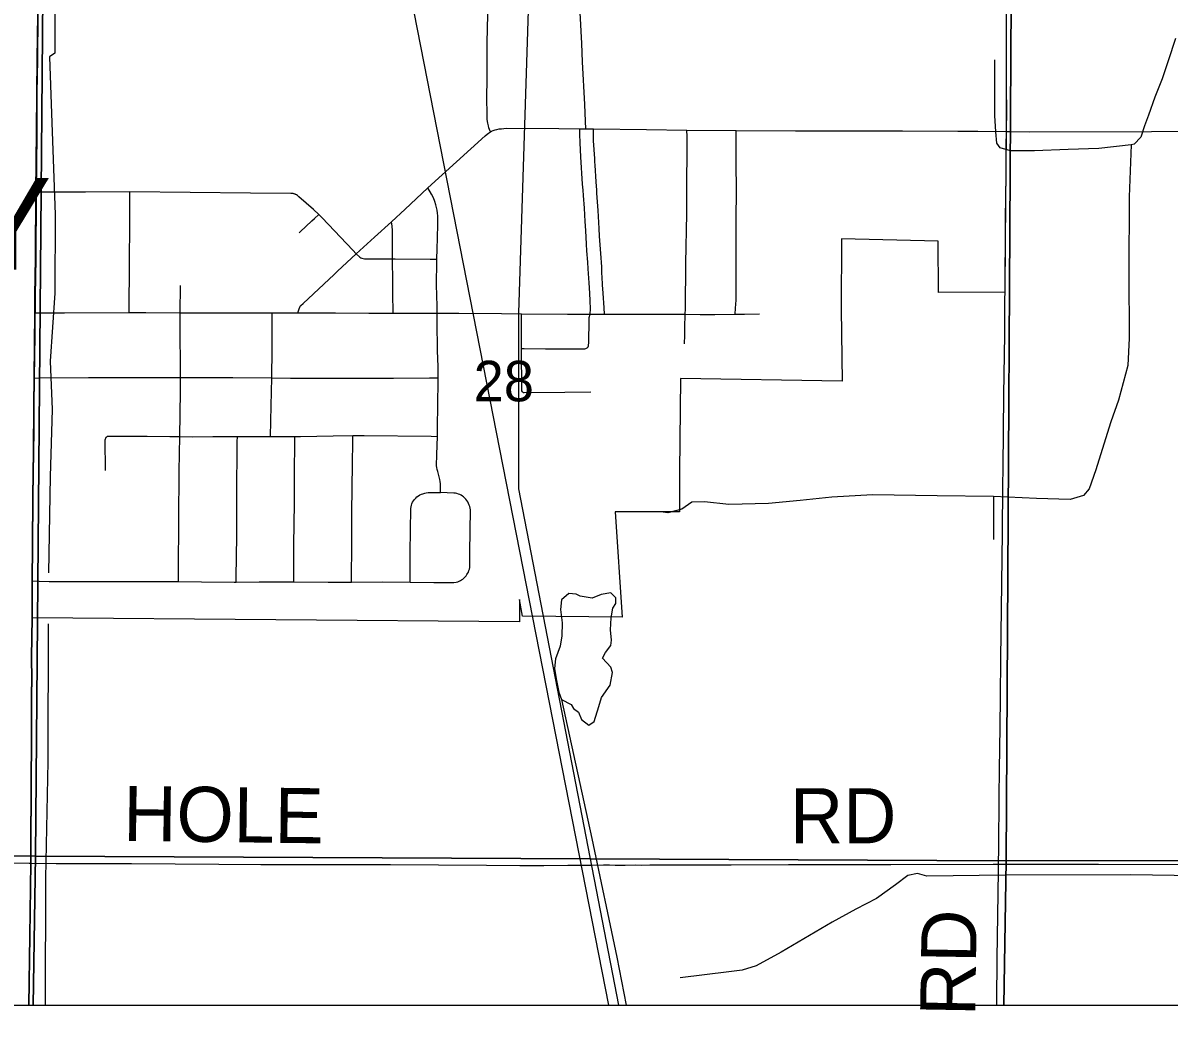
# Model space of a CAD drawing. Extents: x 0 to 34, y 0 to 22.
# Drawn here: x 3.48 to 4.664, y 16.867 to 17.907 of the extents above; entities that cross this region are included whole.
import ezdxf

# ---------------------------------------------------------------- set-up
doc = ezdxf.new("R2010")
doc.units = 0
for name, color, linetype in [('GM_X_City_Street', 7, 'Continuous'), ('GM_X_Corporation', 7, 'Continuous'), ('GM_X_Corporation_Text', 7, 'Continuous'), ('GM_X_County_Road', 7, 'Continuous'), ('GM_X_Minor_Lake', 7, 'Continuous'), ('GM_X_Minor_River', 7, 'Continuous'), ('GM_X_Rail_Line', 7, 'Continuous'), ('GM_X_Section', 7, 'Continuous'), ('GM_X_Section_Text', 7, 'Continuous'), ('GM_X_State_Route', 7, 'Continuous'), ('GM_X_Township_Road', 7, 'Continuous'), ('GM_X_Township_Road_Text', 7, 'Continuous'), ('GM_X_US_Route', 7, 'Continuous'), ('SH_Text', 7, 'Continuous')]:
    doc.layers.add(name, color=color, linetype=linetype)

msp = doc.modelspace()

# ---------------------------------------------------------------- linework, layer by layer
at = {"layer": 'GM_X_City_Street'}
for points in [[(3.963, 17.795), (3.962, 17.7976), (3.9614, 17.7993), (3.9608, 17.8014), (3.9601, 17.8039), (3.9596, 17.8077), (3.9595, 17.8114), (3.9592, 17.832), (3.9594, 17.8479), (3.9596, 17.887), (3.9613, 17.9602), (3.9621, 17.9987), (3.9626, 18.0388), (3.9627, 18.0507)], [(4.0615, 17.7983), (4.0611, 17.8059), (4.0603, 17.8233), (4.0581, 17.8673), (4.0572, 17.8864), (4.0555, 17.9181), (4.0549, 17.9286), (4.0539, 17.9459), (4.0535, 17.9527), (4.053, 17.9627), (4.0514, 17.993), (4.051, 18.0017), (4.0497, 18.024), (4.0492, 18.0399), (4.0488, 18.0504)], [(4.0658, 17.607), (4.0664, 17.6125), (4.0659, 17.6206), (4.0654, 17.6286), (4.0648, 17.6393), (4.0638, 17.6535), (4.0634, 17.6604), (4.0626, 17.6721), (4.0622, 17.679), (4.0613, 17.6932), (4.0607, 17.7025), (4.0599, 17.7162), (4.0591, 17.7292), (4.0586, 17.7347), (4.0581, 17.7412), (4.0564, 17.7693), (4.0556, 17.7836), (4.0554, 17.7927), (4.0554, 17.7983)], [(4.0806, 17.6068), (4.0802, 17.6135), (4.0793, 17.6286), (4.0787, 17.6373), (4.0783, 17.6453), (4.0781, 17.649), (4.078, 17.6508), (4.0779, 17.6533), (4.0778, 17.6557), (4.0769, 17.6694), (4.0757, 17.6873), (4.0751, 17.6953), (4.0747, 17.7014), (4.074, 17.7137), (4.0729, 17.7317), (4.0727, 17.7347), (4.0721, 17.7433), (4.071, 17.7606), (4.0708, 17.7641), (4.0706, 17.7665), (4.0706, 17.7676), (4.0695, 17.7858), (4.0693, 17.7911), (4.0693, 17.7928), (4.0694, 17.7982)], [(4.1632, 17.5763), (4.1635, 17.5851), (4.1637, 17.5931), (4.1639, 17.6069), (4.1642, 17.6123), (4.1647, 17.6596), (4.1656, 17.7104), (4.1657, 17.7436), (4.166, 17.7734), (4.1659, 17.7902), (4.1658, 17.7969)], [(4.2157, 17.6069), (4.2161, 17.6132), (4.2165, 17.6213), (4.2167, 17.6534), (4.2165, 17.6991), (4.2169, 17.7399), (4.2168, 17.7577), (4.2167, 17.7877), (4.2167, 17.7964)], [(3.4939, 17.733), (3.504, 17.7331), (3.545, 17.7332), (3.5907, 17.7334), (3.7152, 17.7321), (3.757, 17.7319), (3.7578, 17.7318), (3.7588, 17.7317), (3.7596, 17.7314), (3.7607, 17.731)], [(3.5899, 17.6085), (3.59, 17.6153), (3.5903, 17.6538), (3.5906, 17.7067), (3.5907, 17.7334)], [(3.8242, 17.6692), (3.8208, 17.673), (3.7893, 17.7062), (3.7857, 17.7096), (3.7801, 17.715), (3.7651, 17.7281), (3.7637, 17.7293), (3.7627, 17.73), (3.7617, 17.7305), (3.7607, 17.731)], [(3.9114, 17.4228), (3.9114, 17.4317), (3.9111, 17.4343), (3.9107, 17.4363), (3.9085, 17.4444), (3.908, 17.4464), (3.9077, 17.4486), (3.9074, 17.4504), (3.9077, 17.4621), (3.9082, 17.4806), (3.9084, 17.4895), (3.909, 17.5378), (3.9089, 17.5412), (3.9088, 17.5525), (3.9087, 17.5611), (3.9084, 17.5689), (3.9082, 17.5756), (3.9079, 17.5928), (3.9078, 17.6079), (3.9078, 17.615), (3.9074, 17.6373), (3.9075, 17.6611), (3.9076, 17.6636), (3.9079, 17.6743), (3.9084, 17.6854), (3.9085, 17.6997), (3.9085, 17.7082), (3.9082, 17.7112), (3.9078, 17.7141), (3.9072, 17.7171), (3.9066, 17.7198), (3.9055, 17.7232), (3.904, 17.727), (3.9022, 17.7306), (3.8984, 17.7373)], [(3.7656, 17.6908), (3.7665, 17.6917), (3.7787, 17.7032), (3.7813, 17.7056), (3.7857, 17.7096)], [(3.8619, 17.6639), (3.8618, 17.6812), (3.8617, 17.6945), (3.8616, 17.6964), (3.8614, 17.6978), (3.8608, 17.7022)], [(3.8242, 17.6692), (3.8281, 17.6657), (3.8291, 17.6651), (3.8303, 17.6646), (3.8315, 17.6643), (3.833, 17.6641), (3.835, 17.6641), (3.8619, 17.6639), (3.8647, 17.6639), (3.9006, 17.6637), (3.9076, 17.6636)], [(3.8624, 17.6079), (3.8622, 17.6286), (3.862, 17.6471), (3.8619, 17.6566), (3.8619, 17.6639)], [(3.6409, 17.3309), (3.6409, 17.343), (3.6416, 17.4448), (3.6422, 17.4806), (3.6428, 17.5269), (3.6428, 17.5416), (3.6429, 17.5513), (3.6427, 17.5896), (3.6426, 17.6084), (3.6428, 17.6363)], [(3.7359, 17.4805), (3.7366, 17.5123), (3.7374, 17.541), (3.7376, 17.5704), (3.7375, 17.6006), (3.7375, 17.6081)], [(3.7641, 17.6081), (3.8031, 17.6081), (3.8373, 17.608), (3.8624, 17.6079), (3.8745, 17.6079), (3.8937, 17.6078), (3.9078, 17.6079), (3.9304, 17.608), (3.9742, 17.6074), (3.995, 17.6072), (4.0424, 17.6067), (4.0658, 17.607), (4.0806, 17.6068), (4.0964, 17.6068), (4.1299, 17.6069), (4.1639, 17.6069), (4.1796, 17.6065), (4.1945, 17.6065), (4.2157, 17.6069), (4.2254, 17.607), (4.2408, 17.6072)], [(3.9959, 17.5268), (3.9952, 17.5278), (3.995, 17.5713), (3.995, 17.5997), (3.995, 17.6072)], [(3.995, 17.5713), (3.9977, 17.5713), (4.0197, 17.5711), (4.0604, 17.5711), (4.0614, 17.5714), (4.0621, 17.5717), (4.0628, 17.5721), (4.0633, 17.5726), (4.0638, 17.5733), (4.0641, 17.5742), (4.0643, 17.5751), (4.0645, 17.5769), (4.0647, 17.6012), (4.0649, 17.6034), (4.0658, 17.607)], [(3.4921, 17.5407), (3.4982, 17.5412), (3.5478, 17.5414), (3.597, 17.5414), (3.6428, 17.5416), (3.6969, 17.5416), (3.7374, 17.541), (3.7565, 17.5408), (3.8628, 17.5409), (3.9, 17.5411), (3.9089, 17.5412)], [(3.9959, 17.5268), (3.9967, 17.5261), (3.9977, 17.5259), (4.0399, 17.5264), (4.0667, 17.5267)], [(3.5654, 17.4454), (3.5653, 17.4773), (3.5655, 17.4781), (3.5658, 17.4788), (3.5663, 17.4799)], [(3.5663, 17.4799), (3.5668, 17.4804), (3.5674, 17.4808), (3.568, 17.481), (3.5687, 17.4811), (3.6086, 17.4808), (3.6319, 17.4807), (3.6422, 17.4806), (3.6551, 17.4804), (3.6763, 17.4807), (3.7018, 17.4806), (3.7235, 17.4805), (3.7359, 17.4805), (3.7484, 17.4806), (3.7611, 17.4807), (3.7669, 17.4807), (3.8007, 17.4813), (3.8208, 17.4815), (3.8325, 17.4816), (3.9019, 17.4808), (3.9082, 17.4806)], [(3.7005, 17.3304), (3.7005, 17.3354), (3.701, 17.3776), (3.7011, 17.4179), (3.7016, 17.4752), (3.7018, 17.4806)], [(3.7599, 17.3305), (3.7599, 17.3373), (3.7601, 17.3687), (3.7605, 17.4118), (3.7605, 17.4469), (3.7609, 17.4708), (3.7611, 17.4807)], [(3.8195, 17.3304), (3.8196, 17.3375), (3.8198, 17.3651), (3.8198, 17.4021), (3.8205, 17.4523), (3.8207, 17.475), (3.8208, 17.4815)], [(3.8799, 17.3301), (3.8799, 17.3371), (3.8801, 17.3609), (3.8809, 17.4063), (3.881, 17.4081), (3.8813, 17.4096), (3.8817, 17.4111), (3.8824, 17.4127), (3.8834, 17.4142), (3.8844, 17.4155), (3.8858, 17.4169), (3.8871, 17.4182), (3.8886, 17.4194), (3.8902, 17.4203), (3.8918, 17.4211), (3.8933, 17.4216), (3.8951, 17.4221), (3.8967, 17.4225), (3.8987, 17.4227), (3.9114, 17.4228)], [(3.9356, 17.3345), (3.9367, 17.3357), (3.9378, 17.3368), (3.9387, 17.3381), (3.9394, 17.3393), (3.9402, 17.3407), (3.9408, 17.3423), (3.9412, 17.3438), (3.9416, 17.3455), (3.9418, 17.3473), (3.9415, 17.3611), (3.9422, 17.405), (3.9421, 17.4067), (3.9417, 17.4082), (3.941, 17.4099), (3.9402, 17.4115), (3.9395, 17.413), (3.9385, 17.4146), (3.9376, 17.4159), (3.9364, 17.417), (3.9352, 17.4182), (3.9341, 17.419), (3.9328, 17.4199), (3.9314, 17.4206), (3.93, 17.4212), (3.9284, 17.4217), (3.9267, 17.4221), (3.925, 17.4222), (3.9114, 17.4228)], [(3.4901, 17.3315), (3.497, 17.3313), (3.5075, 17.3311), (3.5571, 17.3309), (3.582, 17.3308), (3.6292, 17.3308), (3.6409, 17.3309), (3.6646, 17.3306), (3.6982, 17.3304), (3.7005, 17.3304), (3.7242, 17.3305), (3.75, 17.3306), (3.7599, 17.3305), (3.7954, 17.3304), (3.8195, 17.3304), (3.8511, 17.3305), (3.8799, 17.3301), (3.9045, 17.3299), (3.9252, 17.33), (3.9274, 17.3303), (3.9292, 17.3307), (3.9306, 17.3312), (3.9319, 17.3319), (3.9332, 17.3327), (3.9344, 17.3335), (3.9356, 17.3345)]]:
    msp.add_lwpolyline(points, dxfattribs=at)
at = {"layer": 'GM_X_Corporation'}
msp.add_lwpolyline([(4.4959, 18.0466), (4.4954, 17.796), (4.4944, 17.6823), (4.4939, 17.6297), (4.4257, 17.6292), (4.4251, 17.6823), (4.3255, 17.6845), (4.3252, 17.6116), (4.3262, 17.5376), (4.1591, 17.5404), (4.1582, 17.4446), (4.1582, 17.403), (4.0917, 17.4028), (4.099, 17.2941), (3.9962, 17.2953), (3.993, 17.3122), (3.9929, 17.2963), (3.993, 17.2894), (3.4897, 17.2934), (3.4899, 17.3321), (3.4919, 17.5412), (3.4925, 17.6088), (3.4933, 17.665), (3.4936, 17.7336), (3.4944, 17.795), (3.4956, 17.9163)], dxfattribs=at)
at = {"layer": 'GM_X_County_Road'}
for points in [[(3.4939, 17.733), (3.4939, 17.736), (3.4942, 17.7596), (3.4946, 17.7944), (3.4947, 17.8349), (3.4952, 17.8697), (3.4958, 17.9157), (3.4964, 17.9723), (3.4966, 18.0071), (3.497, 18.0326), (3.4975, 18.0561)], [(3.4928, 17.6082), (3.4929, 17.6259), (3.4936, 17.6645), (3.4935, 17.6782), (3.4938, 17.7167), (3.4939, 17.733)], [(3.4921, 17.5407), (3.4927, 17.5848), (3.4928, 17.6082)], [(3.4901, 17.3315), (3.4904, 17.3674), (3.4908, 17.4178), (3.491, 17.4424), (3.4917, 17.4865), (3.4919, 17.5127), (3.4921, 17.5407)], [(3.4899, 17.2938), (3.4899, 17.3064), (3.4901, 17.3315)], [(3.4885, 17.0403), (3.4885, 17.0425), (3.4887, 17.0721), (3.489, 17.105), (3.489, 17.1211), (3.4891, 17.1367), (3.4892, 17.1528), (3.4893, 17.174), (3.4892, 17.1964), (3.4894, 17.2144), (3.4897, 17.2293), (3.4895, 17.2523), (3.4899, 17.2929), (3.4899, 17.2938)], [(3.4867, 16.8935), (3.4875, 16.9645), (3.4882, 17.0142), (3.4885, 17.0403)]]:
    msp.add_lwpolyline(points, dxfattribs=at)
at = {"layer": 'GM_X_Minor_Lake'}
msp.add_line((4.0681, 17.3138), (4.0556, 17.3157), dxfattribs=at)
msp.add_lwpolyline([(4.0556, 17.3157), (4.0515, 17.3177), (4.0439, 17.3186), (4.0362, 17.312), (4.0352, 17.3021), (4.0371, 17.2884), (4.0368, 17.2747), (4.035, 17.2642), (4.0301, 17.251), (4.0291, 17.2412), (4.0311, 17.2286), (4.0335, 17.2168), (4.0363, 17.2091), (4.0464, 17.2039), (4.0486, 17.1997), (4.0538, 17.1962), (4.057, 17.1885), (4.0644, 17.1826), (4.0702, 17.1863), (4.0748, 17.2021), (4.0776, 17.2111), (4.0867, 17.2238), (4.0889, 17.2371), (4.0871, 17.2424), (4.0786, 17.2517), (4.0818, 17.2577), (4.0873, 17.2648), (4.0878, 17.2705), (4.0869, 17.2811), (4.0876, 17.2936), (4.0894, 17.3035), (4.0925, 17.3083), (4.0923, 17.314), (4.0871, 17.3191), (4.0772, 17.3174), (4.0681, 17.3138)], dxfattribs=at)
at = {"layer": 'GM_X_Minor_River'}
for points in [[(3.5164, 18.4352), (3.5149, 18.3401), (3.5141, 18.2475), (3.5142, 18.1295), (3.5133, 18.0316), (3.5132, 17.8764), (3.5078, 17.8723), (3.5098, 17.8139), (3.5136, 17.7098), (3.5131, 17.6286), (3.5084, 17.5585), (3.5105, 17.5083), (3.5084, 17.4393), (3.5067, 17.3399)], [(4.6701, 17.8913), (4.6628, 17.8683), (4.6566, 17.8499), (4.6488, 17.831), (4.6425, 17.8124), (4.6384, 17.8013), (4.6344, 17.7894), (4.6277, 17.7823), (4.6246, 17.7816), (4.591, 17.7779), (4.5594, 17.7767), (4.5245, 17.7756), (4.4999, 17.7755), (4.4893, 17.7786), (4.4857, 17.7834), (4.4848, 17.7952), (4.4837, 17.812), (4.4836, 17.8692)], [(4.6246, 17.7816), (4.6225, 17.7281), (4.6221, 17.6496), (4.6223, 17.582), (4.6209, 17.554), (4.6113, 17.5181), (4.6033, 17.4959), (4.5945, 17.4673), (4.5879, 17.4462), (4.581, 17.4267), (4.5751, 17.4196), (4.5614, 17.4157), (4.5266, 17.4166), (4.4823, 17.4188), (4.424, 17.4195), (4.3574, 17.4203), (4.3153, 17.4179), (4.2826, 17.4145), (4.25, 17.4115), (4.2092, 17.4103), (4.1838, 17.4131), (4.1709, 17.4127), (4.1605, 17.4057), (4.146, 17.4019), (4.1411, 17.4024)], [(4.4823, 17.4188), (4.4823, 17.3744)], [(3.5035, 16.8935), (3.5038, 17.0247), (3.5064, 17.1453), (3.5065, 17.2872)], [(4.0363, 17.2091), (4.0676, 17.0657), (4.0933, 16.9432), (4.103, 16.8935)], [(5.1426, 17.0309), (5.0559, 17.03), (4.9471, 17.0292), (4.8582, 17.0291), (4.7358, 17.0264), (4.6241, 17.0283), (4.4946, 17.028), (4.4135, 17.0269), (4.4037, 17.0295), (4.3938, 17.0274), (4.3811, 17.0179), (4.3614, 17.0039), (4.3403, 16.9927), (4.3158, 16.9792), (4.2631, 16.9482), (4.2374, 16.9344), (4.2229, 16.9299), (4.2092, 16.9279), (4.1587, 16.9219)]]:
    msp.add_lwpolyline(points, dxfattribs=at)
at = {"layer": 'GM_X_Rail_Line'}
for points in [[(3.0707, 20.9), (3.1351, 20.7649), (3.2934, 20.4339), (3.3742, 20.2628), (3.4243, 20.1498), (3.4485, 20.0723), (3.4792, 19.9786), (3.5083, 19.83), (3.6846, 18.9371), (3.8463, 18.1103), (4.0848, 16.8935)], [(4.0191, 20.9), (4.0122, 20.3656), (4.0051, 19.4649), (4.0042, 19.0681), (4.0247, 18.6307), (3.9918, 17.6084), (3.9918, 17.4265), (4.095, 16.8935)]]:
    msp.add_lwpolyline(points, dxfattribs=at)
at = {"layer": 'GM_X_Section'}
for points in [[(3.5019, 18.057), (3.4934, 17.0475), (2.4879, 17.0483), (2.4915, 18.0628)], [(4.5012, 18.0497), (4.4954, 17.0428), (3.4934, 17.0475), (3.5019, 18.057)], [(5.5052, 18.0545), (5.4985, 17.0434), (4.4954, 17.0428), (4.5012, 18.0497)]]:
    msp.add_lwpolyline(points, close=True, dxfattribs=at)
for points in [[(3.4773, 16.1435), (3.4754, 16.0365), (3.4686, 16.0366), (2.4803, 16.0422), (2.4865, 16.4094), (2.4879, 17.0483), (3.4934, 17.0475), (3.4907, 16.8935)], [(3.4907, 16.8935), (3.4934, 17.0475), (4.4954, 17.0428), (4.4929, 16.8935)], [(4.4929, 16.8935), (4.4954, 17.0428), (5.4985, 17.0434), (5.476, 16.0344), (5.457, 16.0346), (4.4786, 16.0375), (4.4803, 16.1435)]]:
    msp.add_lwpolyline(points, dxfattribs=at)
at = {"layer": 'GM_X_State_Route'}
for p, q in [((4.4454, 17.7958), (4.4663, 17.7956)), ((4.4663, 17.7956), (4.4957, 17.7954))]:
    msp.add_line(p, q, dxfattribs=at)
for points in [[(3.4975, 18.0561), (3.497, 18.0326), (3.4966, 18.0071), (3.4964, 17.9723), (3.4958, 17.9157), (3.4952, 17.8697), (3.4947, 17.8349), (3.4946, 17.7944), (3.4942, 17.7596), (3.4939, 17.736), (3.4939, 17.733)], [(3.8051, 17.6511), (3.8242, 17.6692), (3.8432, 17.6864), (3.8608, 17.7022), (3.8748, 17.7153), (3.8921, 17.7313), (3.8984, 17.7373), (3.9576, 17.791), (3.9595, 17.7926), (3.9609, 17.7937), (3.963, 17.795), (3.9641, 17.7956), (3.9657, 17.7963), (3.9677, 17.797), (3.9697, 17.7975), (3.9721, 17.798), (3.9745, 17.7983), (3.9767, 17.7986), (3.9792, 17.7987), (4.0337, 17.7985), (4.0554, 17.7983), (4.0615, 17.7983), (4.0694, 17.7982), (4.1239, 17.7973), (4.1658, 17.7969), (4.2167, 17.7964), (4.2778, 17.7962), (4.3884, 17.7961), (4.4454, 17.7958)], [(4.4957, 17.7954), (4.4991, 17.7954), (4.519, 17.7951), (4.6455, 17.7954), (4.7296, 17.7964), (4.7731, 17.7969), (4.8092, 17.7969), (4.875, 17.7975), (4.9073, 17.7979), (4.9501, 17.7976), (4.9868, 17.7977), (5.0076, 17.7978), (5.066, 17.7979), (5.1163, 17.7981), (5.1723, 17.7982), (5.217, 17.7983), (5.3339, 17.7983), (5.5041, 17.7977)], [(3.4939, 17.733), (3.4938, 17.7167), (3.4935, 17.6782), (3.4936, 17.6645), (3.4929, 17.6259), (3.4928, 17.6082)], [(3.7695, 17.6179), (3.8015, 17.6477), (3.8051, 17.6511)], [(3.4928, 17.6082), (3.5233, 17.6082), (3.5899, 17.6085), (3.5917, 17.6085), (3.607, 17.6085)], [(3.607, 17.6085), (3.6426, 17.6084), (3.6962, 17.6084), (3.7262, 17.6082)], [(3.7262, 17.6082), (3.7375, 17.6081), (3.7473, 17.6081), (3.7641, 17.6081), (3.7653, 17.6124), (3.766, 17.614), (3.7666, 17.615), (3.7673, 17.6159), (3.7695, 17.6179)]]:
    msp.add_lwpolyline(points, dxfattribs=at)
at = {"layer": 'GM_X_Township_Road'}
for points in [[(4.4957, 17.7954), (4.496, 17.8176), (4.4959, 17.8388), (4.4958, 17.868), (4.4961, 17.9965), (4.4966, 18.0464)], [(4.4942, 17.6292), (4.4947, 17.7018), (4.495, 17.7315), (4.4953, 17.7457), (4.4954, 17.7624), (4.4955, 17.781), (4.4957, 17.7954)], [(4.494, 17.6133), (4.4941, 17.6227), (4.4942, 17.6292)], [(4.4875, 17.0392), (4.4878, 17.0562), (4.4883, 17.109), (4.4884, 17.1364), (4.4891, 17.1811), (4.4894, 17.2116), (4.49, 17.2514), (4.4906, 17.3027), (4.4917, 17.3815), (4.492, 17.4292), (4.4924, 17.4485), (4.4931, 17.5237), (4.4939, 17.5858), (4.494, 17.607), (4.494, 17.6133)], [(2.4899, 17.0522), (2.5014, 17.0521), (2.548, 17.0515), (2.604, 17.0508), (2.6723, 17.0498), (2.7438, 17.0491), (2.7966, 17.0484), (2.8526, 17.0478), (2.8681, 17.0476), (2.921, 17.047), (2.952, 17.0465), (2.9614, 17.0463), (2.9987, 17.0459), (3.0919, 17.0449), (3.1447, 17.0443), (3.1851, 17.0439), (3.2411, 17.0432), (3.3343, 17.0421), (3.3623, 17.0417), (3.3965, 17.0412), (3.4617, 17.0405), (3.4866, 17.0403), (3.4885, 17.0403)], [(3.4885, 17.0403), (3.5146, 17.04), (3.5425, 17.0399), (3.5923, 17.0399), (3.6824, 17.0392), (3.7259, 17.0389), (3.7477, 17.0387), (3.816, 17.0389), (3.8596, 17.0388), (3.959, 17.0381), (3.9932, 17.0379), (3.9994, 17.0379), (4.0179, 17.0377), (4.0429, 17.038), (4.0628, 17.0382)], [(4.0628, 17.0382), (4.0667, 17.0382), (4.0796, 17.0385), (4.0857, 17.0384), (4.0917, 17.0382), (4.1021, 17.0382), (4.1126, 17.0384), (4.1187, 17.0382), (4.1276, 17.0384), (4.1401, 17.0385), (4.1467, 17.0384), (4.1587, 17.0386), (4.2115, 17.0386), (4.2706, 17.0389), (4.3297, 17.039), (4.3763, 17.0388), (4.482, 17.0392), (4.4875, 17.0392)], [(4.4856, 16.8935), (4.4857, 16.8976), (4.4862, 16.9418), (4.4871, 17.0089), (4.4874, 17.0326), (4.4875, 17.0392)], [(4.4875, 17.0392), (4.513, 17.0392), (4.5908, 17.0393), (4.7151, 17.039), (4.7773, 17.0386), (4.8643, 17.0384), (5.0197, 17.0392), (5.0663, 17.0396), (5.0881, 17.0395), (5.1037, 17.0391), (5.1192, 17.0385), (5.1254, 17.0383), (5.1471, 17.0377), (5.1626, 17.0374), (5.2123, 17.0371), (5.2558, 17.0372), (5.3242, 17.0377), (5.3957, 17.0379), (5.4361, 17.0378), (5.4765, 17.0381), (5.4947, 17.038)]]:
    msp.add_lwpolyline(points, dxfattribs=at)
at = {"layer": 'GM_X_US_Route'}
for points in [[(3.4865, 16.8935), (3.4873, 16.9651), (3.488, 17.0148), (3.4883, 17.0409), (3.4883, 17.0431), (3.4884, 17.0727), (3.4887, 17.1055), (3.4887, 17.1217), (3.4889, 17.1372), (3.489, 17.1534), (3.4891, 17.1745), (3.489, 17.1969), (3.4892, 17.2149), (3.4895, 17.2298), (3.4892, 17.2528), (3.4897, 17.2934), (3.4897, 17.307), (3.4899, 17.3321), (3.4902, 17.3679), (3.4906, 17.4184), (3.4908, 17.443), (3.4915, 17.4871), (3.4916, 17.5132), (3.4919, 17.5412), (3.4925, 17.5854), (3.4925, 17.6088), (3.4927, 17.6265), (3.4933, 17.665), (3.4933, 17.6787), (3.4936, 17.7173), (3.4936, 17.7336), (3.4936, 17.7365), (3.494, 17.7602), (3.4944, 17.795), (3.4945, 17.8354), (3.495, 17.8702), (3.4956, 17.9163)], [(3.4956, 17.9163), (3.495, 17.8702), (3.4945, 17.8354), (3.4944, 17.795), (3.494, 17.7602), (3.4936, 17.7365), (3.4936, 17.7336), (3.4936, 17.7173), (3.4933, 17.6787), (3.4933, 17.665), (3.4927, 17.6265), (3.4925, 17.6088), (3.4925, 17.5854), (3.4919, 17.5412), (3.4916, 17.5132), (3.4915, 17.4871), (3.4908, 17.443), (3.4906, 17.4184), (3.4902, 17.3679), (3.4899, 17.3321), (3.4897, 17.307), (3.4897, 17.2934), (3.4892, 17.2528), (3.4895, 17.2298), (3.4892, 17.2149), (3.489, 17.1969), (3.4891, 17.1745), (3.489, 17.1534), (3.4889, 17.1372), (3.4887, 17.1217), (3.4887, 17.1055), (3.4884, 17.0727), (3.4883, 17.0431), (3.4883, 17.0409), (3.488, 17.0148), (3.4873, 16.9651), (3.4865, 16.8935)]]:
    msp.add_lwpolyline(points, dxfattribs=at)
at = {"layer": 'SH_Text'}
msp.add_lwpolyline([(3.0426, 16.8935), (5.0426, 16.8935), (5.0426, 16.1435), (3.0426, 16.1435)], close=True, dxfattribs=at)

# ---------------------------------------------------------------- texts
at = {"layer": 'GM_X_Corporation_Text'}
msp.add_text('LUCKEY', height=0.0947, rotation=0, dxfattribs=at).set_placement((3.0031, 17.6527))
at = {"layer": 'GM_X_Section_Text'}
msp.add_text('28', height=0.04186, rotation=0, dxfattribs=at).set_placement((3.9456, 17.5169))
at = {"layer": 'GM_X_Township_Road_Text'}
for s, rotation, p in [('HOLE', 359.2621, (3.5836, 17.0633)), ('RD', 0, (4.2723, 17.0608)), ('RD', 89.0287, (4.4633, 16.8821))]:
    msp.add_text(s, height=0.05682, rotation=rotation, dxfattribs=at).set_placement(p)

doc.saveas('drawing.dxf')
